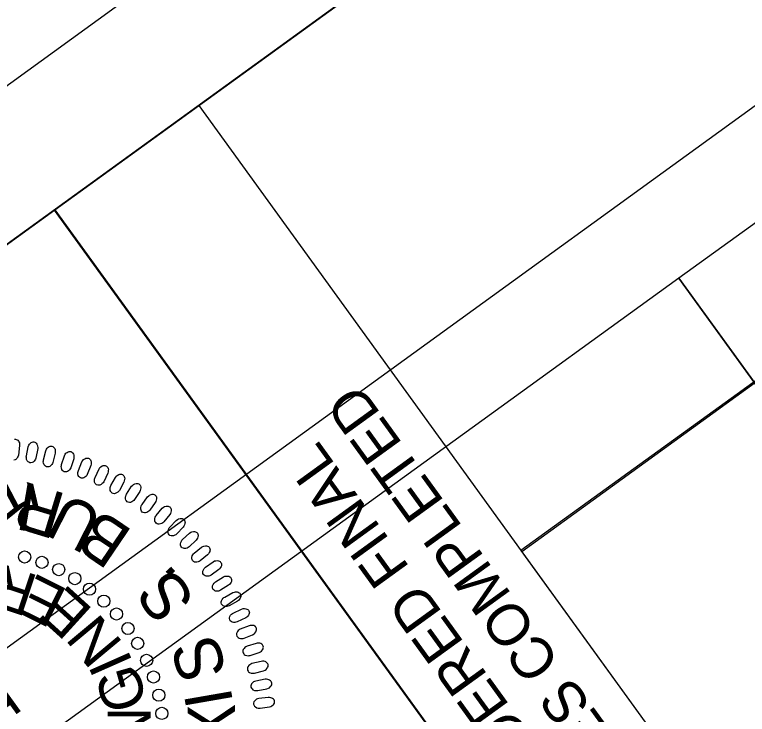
# Model space of a CAD drawing. Extents: x 474925 to 478950, y 494687 to 502905.
# Drawn here: x 475069.3 to 475166, y 502284.1 to 502376.4 of the extents above; entities that cross this region are included whole.
import ezdxf

# ---------------------------------------------------------------- set-up
doc = ezdxf.new("R2010")
doc.units = 0
for name, color, linetype in [('Sheet Layout Plan Border', 7, 'Continuous'), ('Sheet PE Seal Cell', 7, 'Continuous'), ('Sheet Plan CELL', 7, 'Continuous'), ('Sheet Plan Layout CELL', 7, 'Continuous'), ('Sheet Plot Border Inside CELL', 7, 'Continuous'), ('Sheet Plot Border Outside CELL', 7, 'Continuous'), ('Sheet Sticker Exception Certification CELL', 7, 'Continuous'), ('Sheet Sticker Incomplete CELL', 7, 'Continuous')]:
    doc.layers.add(name, color=color, linetype=linetype)

msp = doc.modelspace()

# ---------------------------------------------------------------- linework, layer by layer
at = {"layer": 'Sheet Layout Plan Border'}
for points in [[(476646.384, 501714.386), (476110.18, 502454.921), (476091.748, 502441.575), (476003.493, 502563.461), (475989.428, 502553.276), (475869.086, 502719.476), (475838.053, 502697.006), (475782.546, 502773.666), (475678.649, 502698.454), (475652.98, 502679.873), (475264.351, 502398.541), (475136.14, 502305.707), (475210.951, 502202.387), (475104.173, 502125.071), (475196.466, 501997.607), (475162.674, 501973.139), (475721.996, 501200.68)], [(476646.506, 501714.234), (476022.047, 502576.655), (475989.428, 502553.276), (475869.2, 502719.318), (475838.175, 502696.853), (475782.667, 502773.513), (475678.77, 502698.302), (475653.102, 502679.72), (475264.472, 502398.389), (475136.261, 502305.554), (475211.073, 502202.234), (475104.294, 502124.918), (475196.588, 501997.455), (475162.795, 501972.986), (475722.117, 501200.527)]]:
    msp.add_lwpolyline(points, close=True, dxfattribs=at)
at = {"layer": 'Sheet PE Seal Cell'}
msp.add_lwpolyline([(475069.323, 502320.399), (475069.437, 502320.404), (475069.546, 502320.37), (475069.661, 502320.325), (475069.757, 502320.253), (475069.848, 502320.14), (475069.897, 502320.054), (475069.945, 502319.896), (475069.982, 502319.711), (475069.984, 502319.55), (475069.831, 502318.303), (475069.787, 502318.137), (475069.724, 502318.004), (475069.615, 502317.858), (475069.487, 502317.734), (475069.38, 502317.667), (475069.217, 502317.627)], dxfattribs=at)
for points in [[(475070.877, 502318.183), (475071.109, 502319.388), (475071.187, 502319.597), (475071.265, 502319.724), (475071.407, 502319.869), (475071.523, 502319.959), (475071.649, 502320.015), (475071.759, 502320.035), (475071.873, 502320.033), (475071.979, 502319.992), (475072.091, 502319.94), (475072.182, 502319.862), (475072.266, 502319.744), (475072.31, 502319.654), (475072.348, 502319.495), (475072.373, 502319.307), (475072.364, 502319.146), (475072.134, 502317.911), (475072.08, 502317.749), (475072.009, 502317.62), (475071.891, 502317.48), (475071.755, 502317.365), (475071.643, 502317.305), (475071.478, 502317.275), (475071.328, 502317.285), (475071.189, 502317.352), (475071.095, 502317.421), (475070.989, 502317.543), (475070.904, 502317.731), (475070.872, 502317.921), (475070.867, 502318.053)], [(475073.132, 502317.677), (475073.439, 502318.865), (475073.53, 502319.068), (475073.616, 502319.19), (475073.767, 502319.326), (475073.888, 502319.408), (475074.017, 502319.457), (475074.128, 502319.47), (475074.242, 502319.461), (475074.344, 502319.413), (475074.453, 502319.354), (475074.54, 502319.27), (475074.616, 502319.147), (475074.654, 502319.055), (475074.682, 502318.894), (475074.694, 502318.704), (475074.676, 502318.545), (475074.369, 502317.327), (475074.304, 502317.168), (475074.226, 502317.044), (475074.099, 502316.912), (475073.956, 502316.805), (475073.841, 502316.752), (475073.675, 502316.733), (475073.525, 502316.751), (475073.391, 502316.828), (475073.301, 502316.902), (475073.203, 502317.031), (475073.13, 502317.224), (475073.11, 502317.416), (475073.113, 502317.549)], [(475075.518, 502317.052), (475075.899, 502318.217), (475076.003, 502318.414), (475076.095, 502318.531), (475076.255, 502318.657), (475076.382, 502318.731), (475076.513, 502318.772), (475076.625, 502318.777), (475076.738, 502318.761), (475076.837, 502318.708), (475076.942, 502318.642), (475077.024, 502318.553), (475077.091, 502318.425), (475077.124, 502318.331), (475077.141, 502318.167), (475077.142, 502317.978), (475077.114, 502317.82), (475076.731, 502316.623), (475076.656, 502316.469), (475076.57, 502316.351), (475076.436, 502316.227), (475076.286, 502316.128), (475076.168, 502316.083), (475076.001, 502316.075), (475075.852, 502316.103), (475075.722, 502316.187), (475075.639, 502316.267), (475075.549, 502316.401), (475075.488, 502316.599), (475075.479, 502316.792), (475075.492, 502316.923)], [(475077.734, 502316.256), (475078.188, 502317.396), (475078.303, 502317.585), (475078.403, 502317.696), (475078.571, 502317.812), (475078.701, 502317.878), (475078.835, 502317.911), (475078.947, 502317.91), (475079.059, 502317.886), (475079.155, 502317.826), (475079.256, 502317.754), (475079.331, 502317.66), (475079.391, 502317.529), (475079.417, 502317.432), (475079.424, 502317.268), (475079.414, 502317.079), (475079.376, 502316.923), (475078.917, 502315.753), (475078.834, 502315.604), (475078.74, 502315.491), (475078.598, 502315.375), (475078.442, 502315.287), (475078.322, 502315.249), (475078.154, 502315.251), (475078.008, 502315.288), (475077.884, 502315.381), (475077.805, 502315.466), (475077.724, 502315.605), (475077.676, 502315.807), (475077.679, 502315.999), (475077.7, 502316.13)], [(475079.935, 502315.357), (475080.46, 502316.466), (475080.587, 502316.648), (475080.694, 502316.753), (475080.868, 502316.858), (475081.003, 502316.916), (475081.138, 502316.94), (475081.25, 502316.931), (475081.36, 502316.901), (475081.452, 502316.835), (475081.548, 502316.757), (475081.617, 502316.659), (475081.668, 502316.524), (475081.689, 502316.426), (475081.686, 502316.261), (475081.663, 502316.073), (475081.615, 502315.92), (475081.084, 502314.781), (475080.992, 502314.637), (475080.891, 502314.53), (475080.742, 502314.424), (475080.582, 502314.346), (475080.459, 502314.315), (475080.292, 502314.328), (475080.148, 502314.374), (475080.03, 502314.474), (475079.957, 502314.564), (475079.884, 502314.708), (475079.849, 502314.913), (475079.865, 502315.104), (475079.893, 502315.234)], [(475082.029, 502314.279), (475082.623, 502315.353), (475082.761, 502315.526), (475082.874, 502315.623), (475083.054, 502315.718), (475083.192, 502315.767), (475083.329, 502315.782), (475083.44, 502315.767), (475083.548, 502315.73), (475083.636, 502315.658), (475083.726, 502315.574), (475083.79, 502315.472), (475083.832, 502315.333), (475083.847, 502315.235), (475083.833, 502315.072), (475083.799, 502314.885), (475083.741, 502314.734), (475083.14, 502313.631), (475083.039, 502313.493), (475082.931, 502313.393), (475082.776, 502313.297), (475082.611, 502313.229), (475082.487, 502313.206), (475082.32, 502313.229), (475082.18, 502313.284), (475082.068, 502313.392), (475082.001, 502313.486), (475081.938, 502313.634), (475081.915, 502313.84), (475081.943, 502314.031), (475081.98, 502314.158)], [(475084.093, 502313.146), (475084.753, 502314.18), (475084.902, 502314.345), (475085.021, 502314.435), (475085.207, 502314.518), (475085.347, 502314.558), (475085.485, 502314.565), (475085.594, 502314.542), (475085.7, 502314.499), (475085.783, 502314.422), (475085.868, 502314.332), (475085.925, 502314.226), (475085.959, 502314.085), (475085.967, 502313.986), (475085.943, 502313.823), (475085.897, 502313.64), (475085.83, 502313.493), (475085.161, 502312.43), (475085.051, 502312.299), (475084.938, 502312.205), (475084.777, 502312.119), (475084.607, 502312.061), (475084.482, 502312.046), (475084.318, 502312.079), (475084.18, 502312.144), (475084.076, 502312.257), (475084.015, 502312.357), (475083.961, 502312.508), (475083.952, 502312.715), (475083.991, 502312.904), (475084.036, 502313.028)], [(475086.133, 502311.793), (475086.856, 502312.784), (475087.015, 502312.939), (475087.139, 502313.021), (475087.33, 502313.092), (475087.473, 502313.123), (475087.611, 502313.122), (475087.719, 502313.092), (475087.822, 502313.042), (475087.9, 502312.96), (475087.979, 502312.866), (475088.029, 502312.756), (475088.054, 502312.613), (475088.056, 502312.513), (475088.022, 502312.353), (475087.964, 502312.172), (475087.888, 502312.03), (475087.154, 502311.011), (475087.036, 502310.887), (475086.917, 502310.801), (475086.751, 502310.725), (475086.579, 502310.678), (475086.452, 502310.671), (475086.29, 502310.715), (475086.158, 502310.787), (475086.061, 502310.907), (475086.006, 502311.01), (475085.961, 502311.165), (475085.965, 502311.372), (475086.017, 502311.557), (475086.068, 502311.679)], [(475088.021, 502310.33), (475088.805, 502311.274), (475088.973, 502311.419), (475089.103, 502311.493), (475089.298, 502311.552), (475089.442, 502311.574), (475089.58, 502311.564), (475089.686, 502311.528), (475089.785, 502311.471), (475089.858, 502311.385), (475089.931, 502311.285), (475089.974, 502311.172), (475089.99, 502311.028), (475089.985, 502310.929), (475089.941, 502310.771), (475089.873, 502310.595), (475089.788, 502310.457), (475088.991, 502309.486), (475088.865, 502309.37), (475088.742, 502309.291), (475088.57, 502309.226), (475088.395, 502309.19), (475088.269, 502309.191), (475088.111, 502309.245), (475087.982, 502309.325), (475087.893, 502309.452), (475087.845, 502309.557), (475087.81, 502309.714), (475087.827, 502309.921), (475087.89, 502310.103), (475087.949, 502310.221)], [(475089.797, 502308.794), (475090.639, 502309.687), (475090.816, 502309.821), (475090.95, 502309.887), (475091.148, 502309.934), (475091.294, 502309.946), (475091.431, 502309.928), (475091.534, 502309.885), (475091.629, 502309.822), (475091.696, 502309.731), (475091.763, 502309.627), (475091.799, 502309.512), (475091.806, 502309.367), (475091.795, 502309.269), (475091.741, 502309.113), (475091.662, 502308.942), (475091.569, 502308.81), (475090.712, 502307.891), (475090.58, 502307.783), (475090.451, 502307.712), (475090.277, 502307.658), (475090.1, 502307.632), (475089.973, 502307.641), (475089.819, 502307.705), (475089.696, 502307.794), (475089.615, 502307.925), (475089.573, 502308.033), (475089.548, 502308.193), (475089.578, 502308.398), (475089.652, 502308.576), (475089.719, 502308.69)], [(475091.487, 502307.16), (475092.383, 502307.998), (475092.569, 502308.121), (475092.706, 502308.178), (475092.907, 502308.212), (475093.054, 502308.216), (475093.189, 502308.189), (475093.289, 502308.14), (475093.38, 502308.071), (475093.442, 502307.976), (475093.502, 502307.868), (475093.53, 502307.751), (475093.529, 502307.606), (475093.511, 502307.508), (475093.448, 502307.356), (475093.358, 502307.19), (475093.257, 502307.065), (475092.344, 502306.201), (475092.205, 502306.102), (475092.072, 502306.039), (475091.894, 502305.996), (475091.716, 502305.982), (475091.591, 502305.998), (475091.44, 502306.072), (475091.323, 502306.168), (475091.251, 502306.304), (475091.216, 502306.415), (475091.201, 502306.575), (475091.244, 502306.778), (475091.329, 502306.951), (475091.403, 502307.06)], [(475093.032, 502305.358), (475093.979, 502306.138), (475094.172, 502306.249), (475094.312, 502306.297), (475094.515, 502306.318), (475094.661, 502306.314), (475094.794, 502306.277), (475094.891, 502306.222), (475094.978, 502306.148), (475095.033, 502306.049), (475095.086, 502305.937), (475095.107, 502305.819), (475095.097, 502305.674), (475095.073, 502305.578), (475095, 502305.431), (475094.9, 502305.27), (475094.791, 502305.152), (475093.826, 502304.346), (475093.681, 502304.256), (475093.545, 502304.202), (475093.364, 502304.17), (475093.185, 502304.167), (475093.062, 502304.192), (475092.916, 502304.275), (475092.806, 502304.378), (475092.742, 502304.518), (475092.713, 502304.631), (475092.709, 502304.792), (475092.764, 502304.992), (475092.86, 502305.159), (475092.941, 502305.264)], [(475094.519, 502303.512), (475095.513, 502304.231), (475095.712, 502304.329), (475095.857, 502304.369), (475096.06, 502304.378), (475096.206, 502304.363), (475096.336, 502304.319), (475096.429, 502304.258), (475096.511, 502304.178), (475096.561, 502304.076), (475096.607, 502303.962), (475096.62, 502303.842), (475096.6, 502303.698), (475096.571, 502303.603), (475096.489, 502303.461), (475096.379, 502303.307), (475096.262, 502303.196), (475095.249, 502302.453), (475095.098, 502302.372), (475094.959, 502302.327), (475094.777, 502302.305), (475094.598, 502302.314), (475094.476, 502302.347), (475094.336, 502302.439), (475094.232, 502302.549), (475094.177, 502302.693), (475094.156, 502302.807), (475094.161, 502302.968), (475094.229, 502303.164), (475094.336, 502303.324), (475094.423, 502303.424)], [(475095.841, 502301.564), (475096.878, 502302.219), (475097.083, 502302.305), (475097.23, 502302.336), (475097.433, 502302.331), (475097.578, 502302.308), (475097.705, 502302.256), (475097.795, 502302.189), (475097.871, 502302.103), (475097.914, 502301.999), (475097.953, 502301.882), (475097.958, 502301.762), (475097.929, 502301.62), (475097.894, 502301.526), (475097.804, 502301.389), (475097.684, 502301.243), (475097.561, 502301.139), (475096.503, 502300.461), (475096.348, 502300.39), (475096.205, 502300.353), (475096.023, 502300.344), (475095.845, 502300.363), (475095.725, 502300.403), (475095.591, 502300.504), (475095.494, 502300.62), (475095.448, 502300.768), (475095.435, 502300.882), (475095.451, 502301.043), (475095.53, 502301.235), (475095.646, 502301.388), (475095.74, 502301.482)], [(475097.04, 502299.571), (475098.117, 502300.16), (475098.327, 502300.232), (475098.475, 502300.254), (475098.677, 502300.237), (475098.82, 502300.204), (475098.944, 502300.144), (475099.029, 502300.072), (475099.1, 502299.983), (475099.136, 502299.875), (475099.168, 502299.756), (475099.166, 502299.635), (475099.128, 502299.496), (475099.087, 502299.405), (475098.988, 502299.274), (475098.859, 502299.135), (475098.73, 502299.039), (475097.632, 502298.429), (475097.472, 502298.368), (475097.327, 502298.34), (475097.145, 502298.342), (475096.968, 502298.373), (475096.852, 502298.42), (475096.724, 502298.529), (475096.635, 502298.651), (475096.598, 502298.801), (475096.591, 502298.917), (475096.618, 502299.076), (475096.709, 502299.262), (475096.835, 502299.408), (475096.934, 502299.496)], [(475098.164, 502297.464), (475099.275, 502297.984), (475099.489, 502298.043), (475099.638, 502298.055), (475099.839, 502298.025), (475099.98, 502297.983), (475100.099, 502297.916), (475100.18, 502297.838), (475100.245, 502297.745), (475100.275, 502297.635), (475100.298, 502297.514), (475100.289, 502297.394), (475100.243, 502297.257), (475100.196, 502297.169), (475100.089, 502297.044), (475099.951, 502296.914), (475099.817, 502296.826), (475098.682, 502296.287), (475098.518, 502296.235), (475098.373, 502296.217), (475098.191, 502296.23), (475098.017, 502296.272), (475097.903, 502296.327), (475097.783, 502296.443), (475097.701, 502296.571), (475097.674, 502296.723), (475097.675, 502296.839), (475097.71, 502296.996), (475097.814, 502297.176), (475097.948, 502297.313), (475098.052, 502297.395)], [(475099.591, 502294.149), (475100.733, 502294.598), (475100.922, 502294.713), (475101.034, 502294.813), (475101.151, 502294.98), (475101.218, 502295.11), (475101.25, 502295.244), (475101.249, 502295.356), (475101.227, 502295.467), (475101.167, 502295.564), (475101.095, 502295.665), (475101.002, 502295.74), (475100.87, 502295.801), (475100.774, 502295.828), (475100.61, 502295.835), (475100.421, 502295.825), (475100.264, 502295.787), (475099.093, 502295.335), (475098.943, 502295.251), (475098.83, 502295.158), (475098.714, 502295.016), (475098.625, 502294.861), (475098.587, 502294.741), (475098.588, 502294.573), (475098.625, 502294.427), (475098.717, 502294.302), (475098.801, 502294.223), (475098.941, 502294.141), (475099.142, 502294.093), (475099.334, 502294.095), (475099.465, 502294.115)], [(475100.414, 502291.865), (475101.582, 502292.242), (475101.779, 502292.345), (475101.896, 502292.437), (475102.023, 502292.596), (475102.098, 502292.722), (475102.139, 502292.854), (475102.145, 502292.965), (475102.129, 502293.078), (475102.076, 502293.178), (475102.01, 502293.283), (475101.922, 502293.365), (475101.794, 502293.433), (475101.7, 502293.466), (475101.537, 502293.484), (475101.348, 502293.485), (475101.189, 502293.458), (475099.991, 502293.079), (475099.836, 502293.005), (475099.718, 502292.92), (475099.594, 502292.786), (475099.495, 502292.636), (475099.449, 502292.519), (475099.44, 502292.351), (475099.467, 502292.203), (475099.551, 502292.073), (475099.631, 502291.989), (475099.764, 502291.898), (475099.962, 502291.837), (475100.154, 502291.828), (475100.287, 502291.839)], [(475100.979, 502289.547), (475102.168, 502289.85), (475102.371, 502289.94), (475102.494, 502290.025), (475102.631, 502290.175), (475102.713, 502290.296), (475102.762, 502290.425), (475102.775, 502290.536), (475102.767, 502290.65), (475102.72, 502290.753), (475102.661, 502290.862), (475102.578, 502290.949), (475102.455, 502291.025), (475102.363, 502291.064), (475102.202, 502291.092), (475102.013, 502291.106), (475101.852, 502291.088), (475100.633, 502290.785), (475100.474, 502290.722), (475100.351, 502290.643), (475100.218, 502290.518), (475100.11, 502290.375), (475100.057, 502290.26), (475100.037, 502290.093), (475100.055, 502289.943), (475100.131, 502289.809), (475100.205, 502289.72), (475100.333, 502289.621), (475100.527, 502289.547), (475100.718, 502289.526), (475100.85, 502289.529)], [(475101.41, 502287.232), (475102.615, 502287.46), (475102.824, 502287.537), (475102.952, 502287.614), (475103.098, 502287.756), (475103.188, 502287.872), (475103.245, 502287.997), (475103.265, 502288.107), (475103.263, 502288.221), (475103.223, 502288.327), (475103.172, 502288.439), (475103.094, 502288.531), (475102.976, 502288.615), (475102.886, 502288.66), (475102.727, 502288.698), (475102.539, 502288.724), (475102.378, 502288.716), (475101.142, 502288.49), (475100.979, 502288.436), (475100.851, 502288.366), (475100.711, 502288.249), (475100.594, 502288.113), (475100.534, 502288.002), (475100.505, 502287.837), (475100.513, 502287.686), (475100.579, 502287.547), (475100.648, 502287.453), (475100.769, 502287.347), (475100.958, 502287.261), (475101.147, 502287.228), (475101.28, 502287.223)], [(475101.722, 502284.915), (475102.939, 502285.067), (475103.152, 502285.131), (475103.285, 502285.2), (475103.439, 502285.332), (475103.536, 502285.442), (475103.601, 502285.563), (475103.628, 502285.672), (475103.633, 502285.786), (475103.6, 502285.894), (475103.556, 502286.009), (475103.484, 502286.106), (475103.371, 502286.197), (475103.285, 502286.247), (475103.128, 502286.295), (475102.942, 502286.332), (475102.781, 502286.335), (475101.534, 502286.187), (475101.368, 502286.144), (475101.235, 502286.082), (475101.088, 502285.974), (475100.963, 502285.845), (475100.896, 502285.739), (475100.856, 502285.576), (475100.855, 502285.425), (475100.913, 502285.282), (475100.975, 502285.184), (475101.089, 502285.07), (475101.273, 502284.973), (475101.459, 502284.927), (475101.591, 502284.914)]]:
    msp.add_lwpolyline(points, close=True, dxfattribs=at)
for centre in [(475070.645, 502304.852), (475072.927, 502304.145), (475075.141, 502303.191), (475077.263, 502302.004), (475079.207, 502300.609), (475081.091, 502299.024), (475082.759, 502297.331), (475084.279, 502295.433), (475085.559, 502293.46), (475086.739, 502291.218), (475087.641, 502289.02), (475088.34, 502286.627), (475088.753, 502284.222)]:
    msp.add_circle(centre, 0.801, dxfattribs=at)
at = {"layer": 'Sheet Plan CELL'}
for points in [[(474953.05, 502262.647), (475832.788, 501047.669), (476683.252, 501663.47), (475803.528, 502878.428)], [(476683.281, 501663.491), (475832.823, 501047.663), (475070.379, 502100.597), (475191.917, 502188.605), (475074.61, 502350.635), (475803.528, 502878.428)], [(475042.137, 502203.66), (474983.486, 502284.639), (475074.61, 502350.635), (475133.268, 502269.646)]]:
    msp.add_lwpolyline(points, close=True, dxfattribs=at)
at = {"layer": 'Sheet Plan Layout CELL'}
for points in [[(475865.423, 501002.639), (476715.852, 501618.446), (475836.137, 502833.394), (475156.97, 502341.626), (475297.285, 502147.842), (475125.987, 502023.809)], [(475297.285, 502147.842), (475156.955, 502341.646), (474985.643, 502217.634), (475125.987, 502023.809)]]:
    msp.add_lwpolyline(points, close=True, dxfattribs=at)
at = {"layer": 'Sheet Plot Border Inside CELL'}
msp.add_lwpolyline([(476807.904, 501495.6), (475830.83, 502844.985), (474976.319, 502226.269), (475953.391, 500876.866)], close=True, dxfattribs=at)
at = {"layer": 'Sheet Plot Border Outside CELL'}
msp.add_lwpolyline([(475811.793, 502905.401), (476799.127, 501541.824), (475912.215, 500899.631), (474924.88, 502263.208)], close=True, dxfattribs=at)
at = {"layer": 'Sheet Sticker Exception Certification CELL'}
for p, q in [((475074.61, 502350.635), (475093.644, 502364.418)), ((475074.61, 502350.635), (475093.644, 502364.418)), ((475093.634, 502364.41), (475210.951, 502202.387)), ((475093.634, 502364.41), (475210.951, 502202.387)), ((475191.917, 502188.605), (475074.6, 502350.628)), ((475191.917, 502188.605), (475074.6, 502350.628))]:
    msp.add_line(p, q, dxfattribs=at)

# ---------------------------------------------------------------- texts
at = {"layer": 'Sheet PE Seal Cell'}
for s, height, rotation, p in [('K', 6.236, 170.33002, (475072.472, 502314.327)), ('R', 6.236, 163.05499, (475076.305, 502313.113)), ('U', 6.236, 152.95514, (475081.342, 502310.705)), ('B', 6.236, 145.8383, (475085.097, 502308.215)), ('R', 5.669, 161.57098, (475072.645, 502302.323)), ('.', 6.236, 132.13569, (475091.015, 502302.423)), ('E', 5.669, 153.63118, (475076.533, 502300.47)), ('S', 6.236, 125.29003, (475093.344, 502299.123)), ('E', 5.669, 137.75159, (475079.829, 502297.832)), ('N', 5.669, 129.81179, (475083.75, 502293.451)), ('46155', 6.2363, 125.88878, (475075.939, 502276.488)), ('S', 6.236, 106.69483, (475097.398, 502289.563)), ('I', 5.669, 113.93219, (475084.982, 502290.943)), ('G', 5.669, 105.9924, (475086.915, 502285.394)), ('I', 6.236, 99.84918, (475098.171, 502285.608)), ('X', 6.236, 90.90186, (475098.477, 502279.967)), ('N', 5.669, 90.1128, (475087.275, 502279.612))]:
    msp.add_text(s, height=height, rotation=rotation, dxfattribs=at).set_placement(p)
at = {"layer": 'Sheet Sticker Exception Certification CELL'}
for s, p in [('UNLESS ALL SIGNATURES COMPLETED', (475198.041, 502212.792)), ('UNLESS ALL SIGNATURES COMPLETED', (475198.041, 502212.792)), ('DOCUMENT NOT CONSIDERED FINAL', (475187.939, 502211.739)), ('DOCUMENT NOT CONSIDERED FINAL', (475187.939, 502211.739))]:
    msp.add_text(s, height=5.5, rotation=125.90742, dxfattribs=at).set_placement(p)
at = {"layer": 'Sheet Sticker Incomplete CELL'}
for s, height, p in [('INCOMPLETE PLANS', 11.52, (475116.078, 502177.504)), ('DO NOT USE FOR R/W ACQUISITION', 5.76, (475119.801, 502184.213))]:
    msp.add_text(s, height=height, rotation=125.90742, dxfattribs=at).set_placement(p)

doc.saveas('drawing.dxf')
